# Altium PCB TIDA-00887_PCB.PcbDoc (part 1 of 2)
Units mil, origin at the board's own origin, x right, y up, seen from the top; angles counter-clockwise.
Board outline 2665 x 2727 mil, 4 copper layers (Top Layer, GND, 3p3V, Bottom Layer), stack 61.2 mil thick; 96 components, 53 nets, 301 pads, 167 vias.
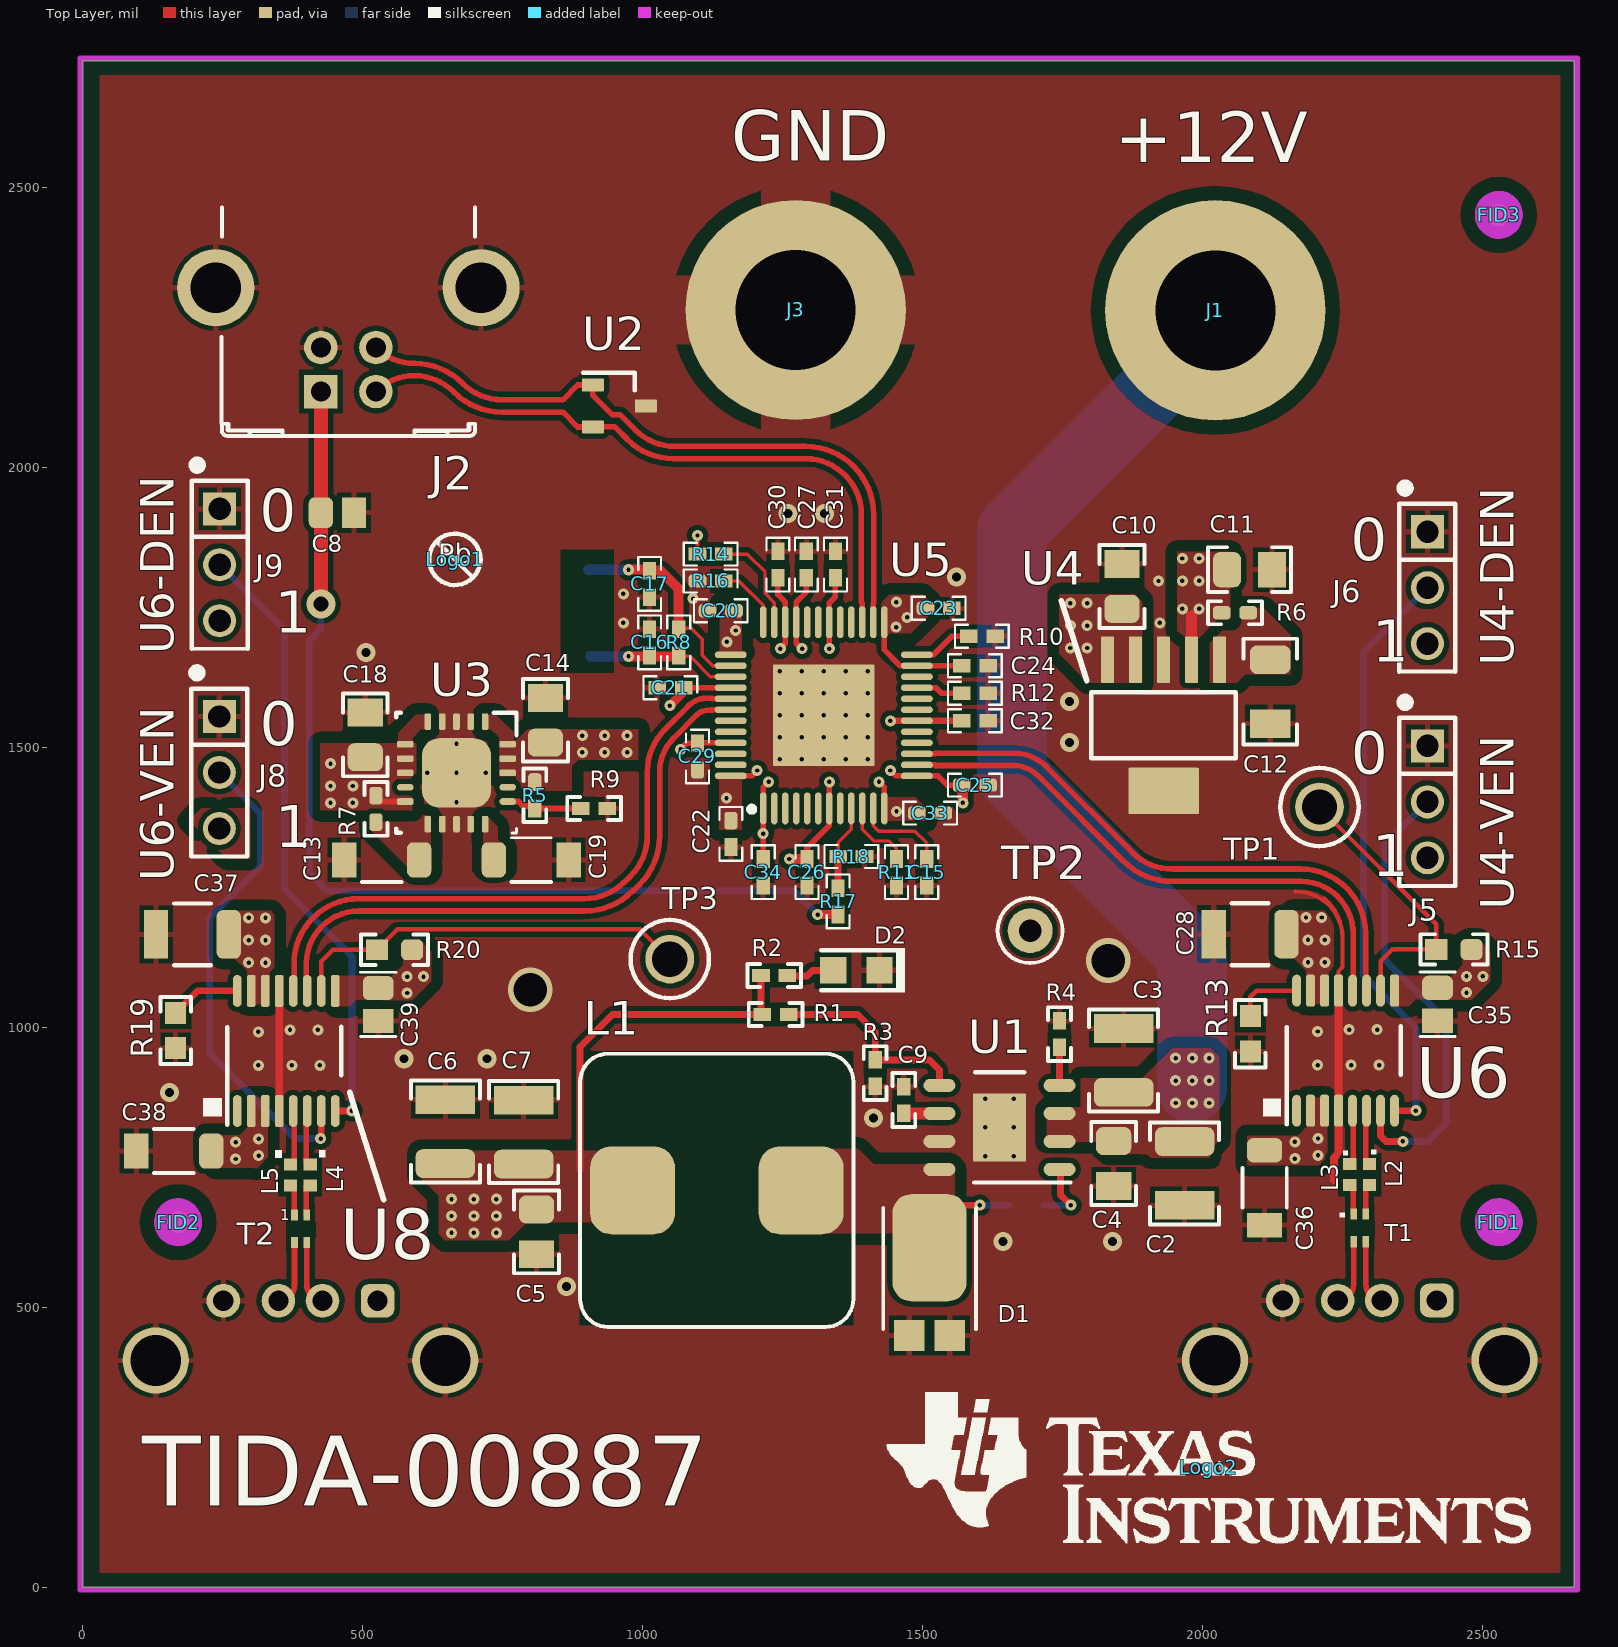
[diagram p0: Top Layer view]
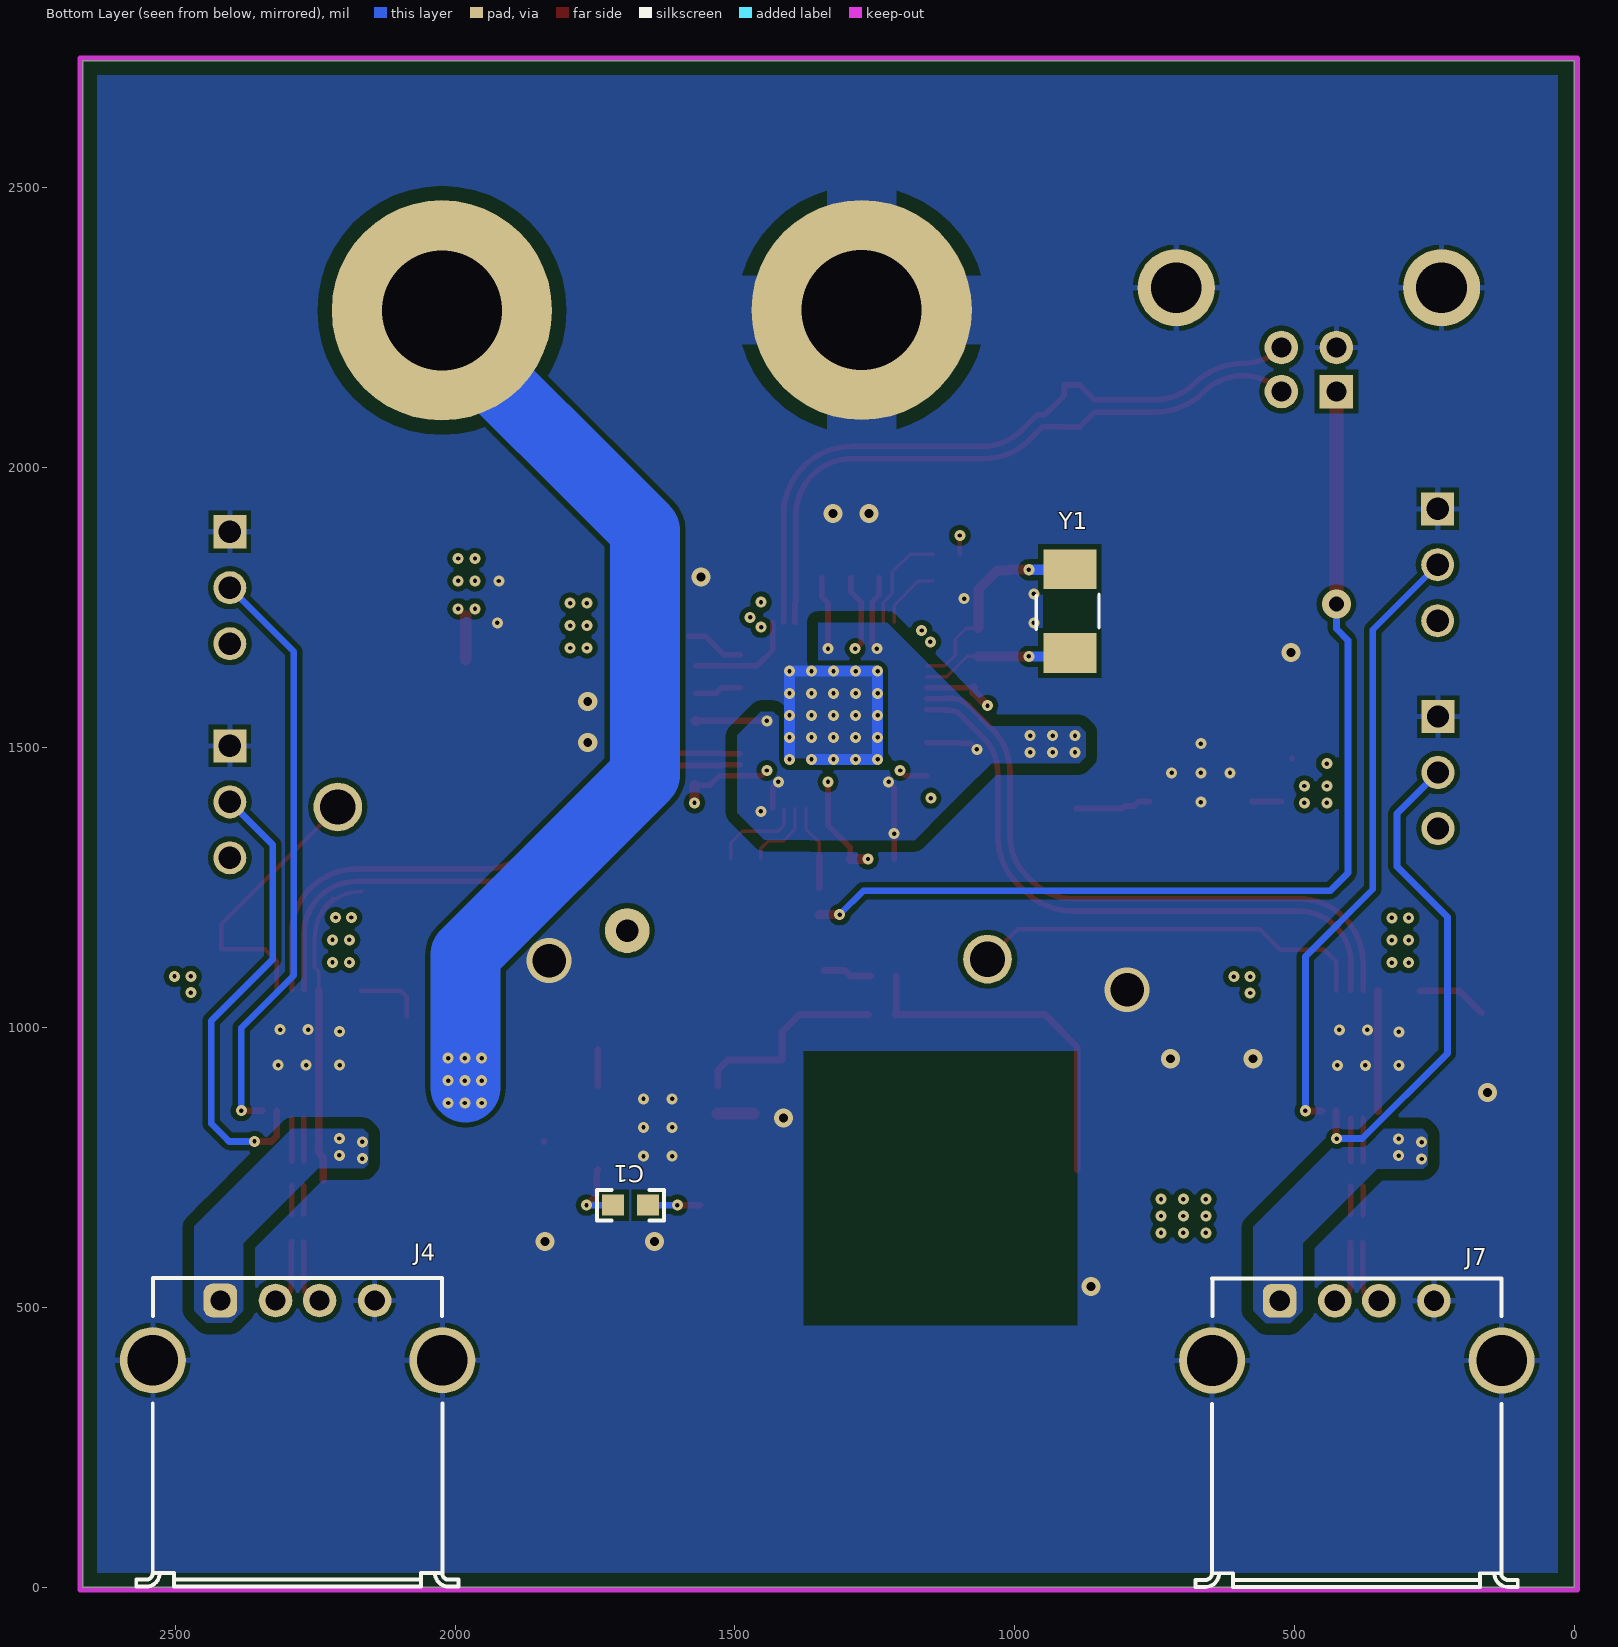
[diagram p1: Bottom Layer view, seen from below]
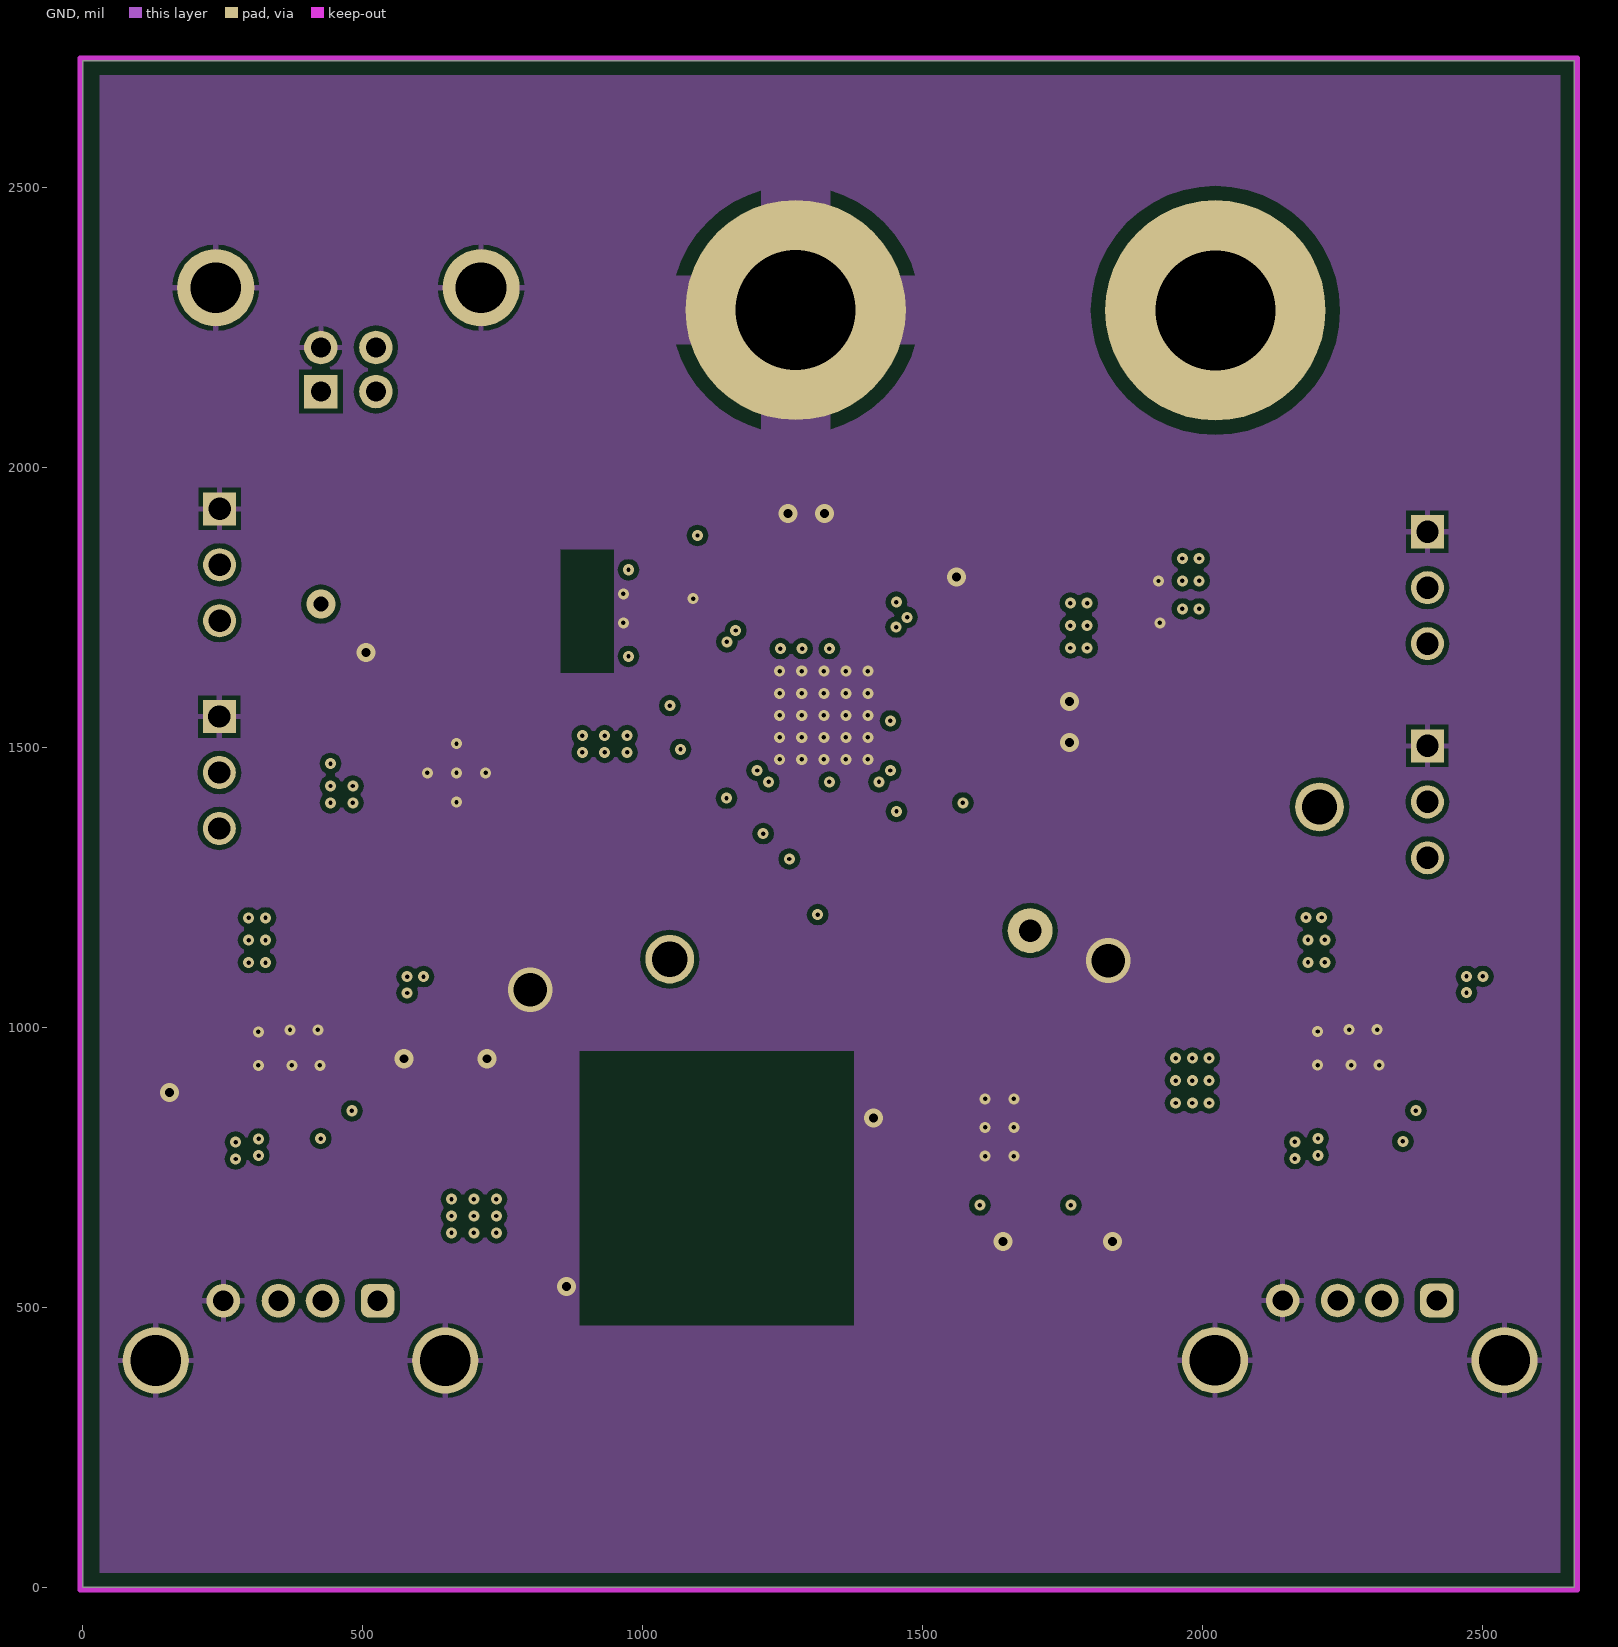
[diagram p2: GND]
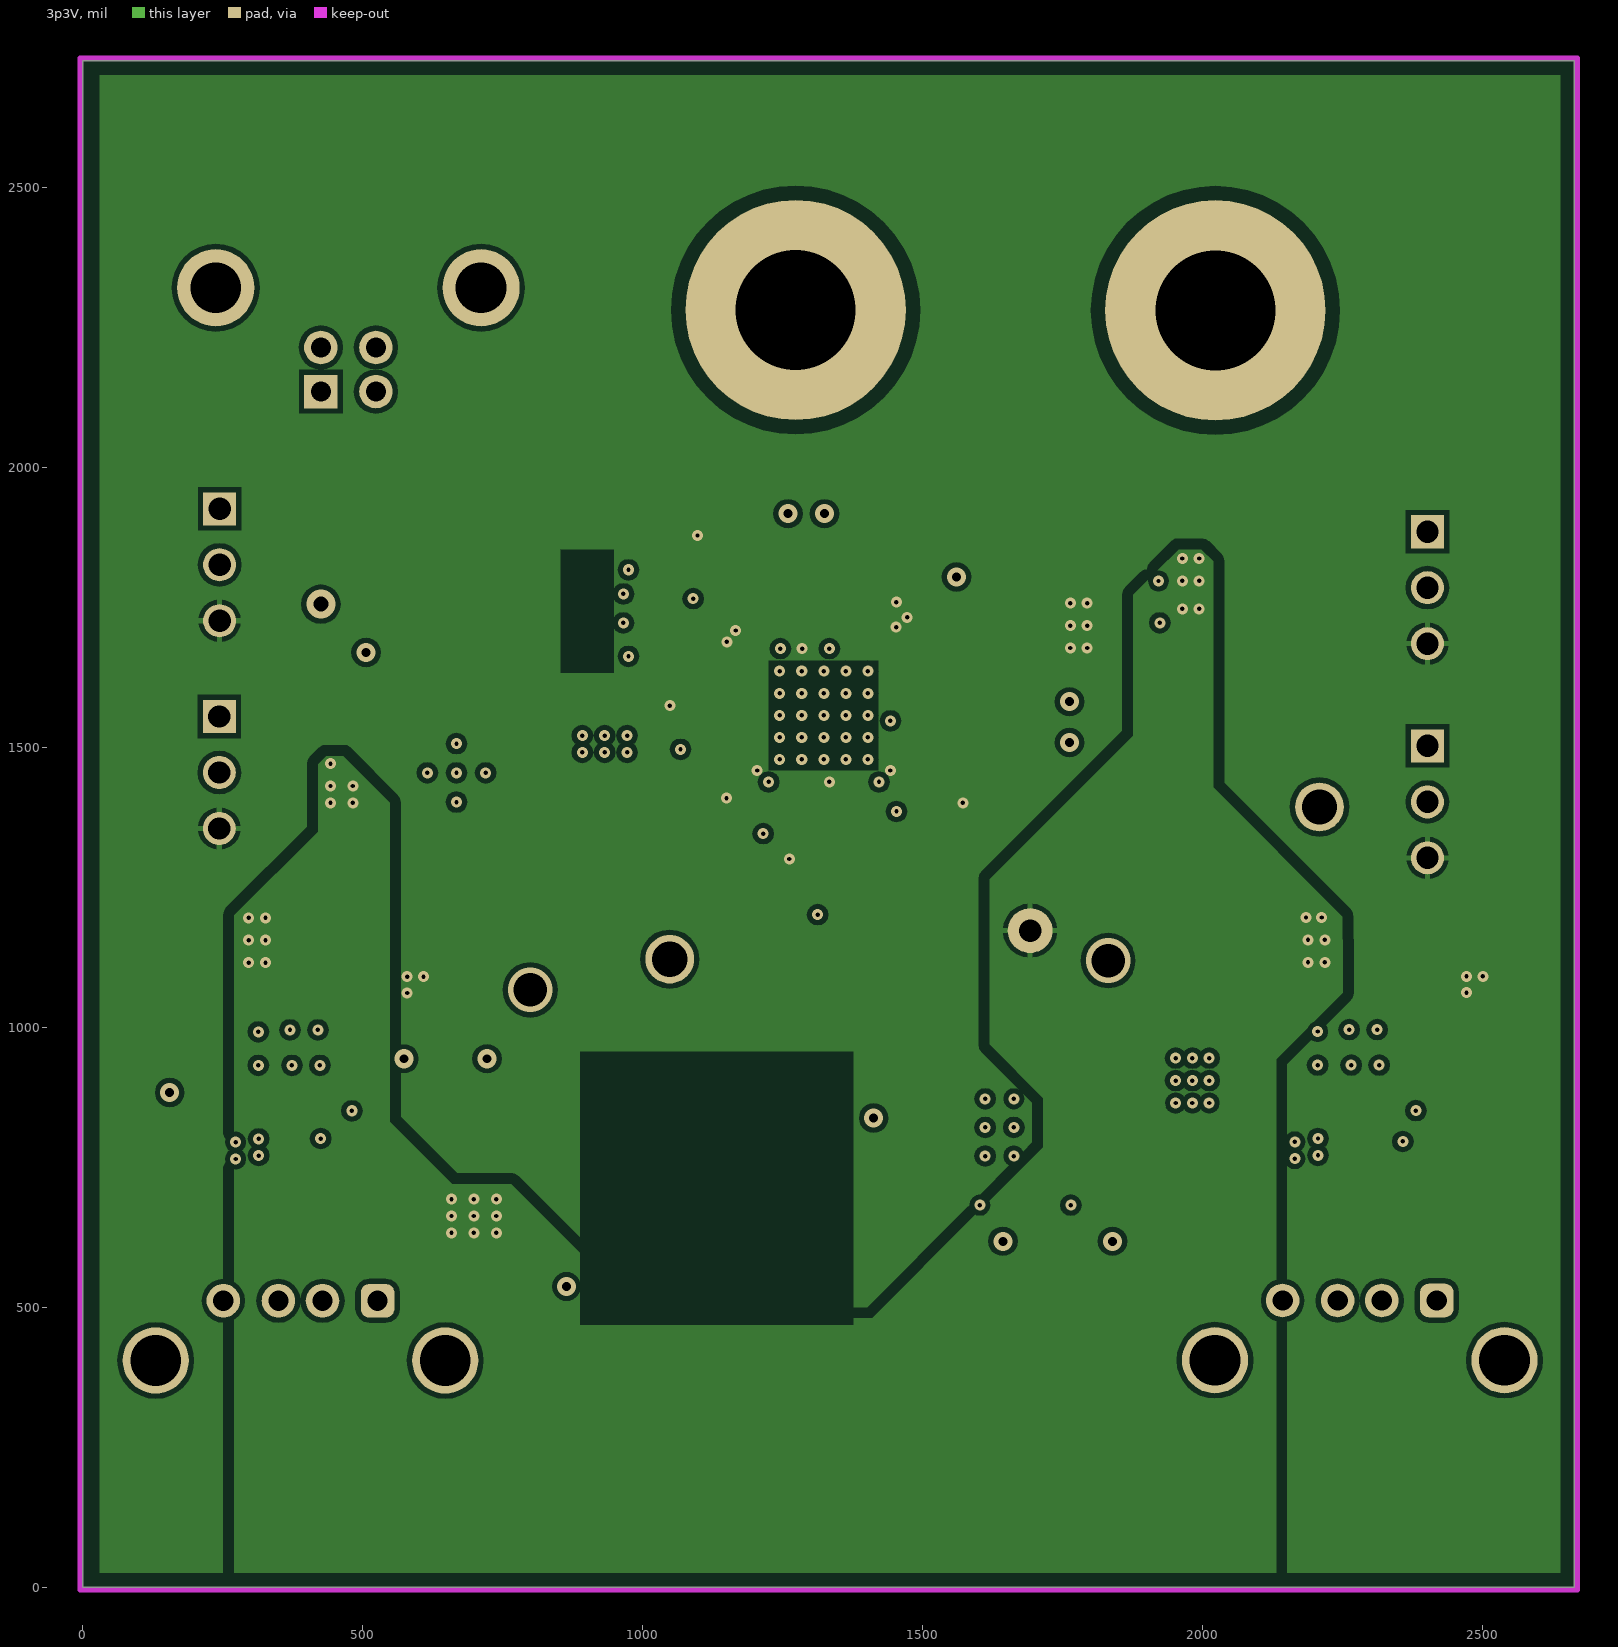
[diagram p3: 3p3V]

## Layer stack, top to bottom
Top Solder: solder mask 0.4, Solder Resist, Dk 3.5
Top Layer: signal copper 1.417
Dielectric1: core 5.5, FR408HR, Dk 3.6
GND: signal copper 1.417
Dielectric 2: prepreg 44.532, FR4, Dk 4.2
3p3V: signal copper 1.417
Dielectric 3: core 5.5, FR408HR, Dk 3.6
Bottom Layer: signal copper 1.417
Bottom Solder: solder mask 0.4, Solder Resist, Dk 3.5

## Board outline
0,0 2665,0 2665,2727 0,2727

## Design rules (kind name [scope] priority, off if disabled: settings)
AcuteAngle [All] p1: minimum=4.50000000000000E+0001 checktracksonly=FALSE
AssemblyTestPointUsage [All] p1: valid=2
Clearance Clearance_Poly_to_Poly_Cap [InPolygon and InNet('NetC7_2') vs InPolygon] p1: gap=5
Clearance Clearance_Keepouts [((IsTrack Or IsArc) And Not InPoly) And IsFree and IsKeepOut vs ((IsTrack Or IsArc) And Not InPoly) And IsFree and IsKeepOut] p2: gap=0
Clearance Clearance_BoardEdge_MountingHoles [OnCopper and InComponentClass('Mounting Holes') vs IsKeepOut] p3: gap=40
Clearance Clearance_BoardEdge_Poly [OnCopper and InPoly vs IsKeepOut] p4: gap=25
Clearance Clearance_BoardEdge [OnCopper and Not InComponentClass('Logo') and not InComponentClass('FiducialMark') and not InRegion(1000,500,4000,800) and Not IsKeepout vs IsKeepOut] p5: gap=62
Clearance Clearance_Poly_GND_J3 [InPadClass('GND')] p6: gap=25
Clearance Clearance_Poly_to_Poly [InPolygon and not InPolygonClass('Star') vs InPolygon] p7: gap=20
Clearance Clearance_Poly [InPolygon and not InPolygonClass('Star')] p8: gap=9
Clearance [All] p9: gap=3.93
ComponentClearance ComponentClearance_BigCap [InComponentClass('BigCap')] p1: gap=0 collisioncheckmode=3 verticalgap=0 showdistances=FALSE
ComponentClearance ComponentClearance_MountingHoles_FiducialMarks [InComponentClass('Mounting Holes') vs InComponentClass('FiducialMark')] p2: gap=50 collisioncheckmode=3 verticalgap=11.3 showdistances=FALSE
ComponentClearance ComponentClearance_Shunt [InComponentClass('Header') vs InComponentClass('Shunt')] p3: gap=0 collisioncheckmode=3 verticalgap=0 showdistances=FALSE
ComponentClearance ComponentClearance_Logo [InComponentClass('Logo')] p4: gap=25 collisioncheckmode=3 verticalgap=11.2 showdistances=FALSE
ComponentClearance ComponentClearance_ScrewToNut [(HasFootprint('NY PMS 440 0025 PH')) vs (HasFootprint('Keystone_1902C'))] p5: gap=5 collisioncheckmode=3 verticalgap=11.1 showdistances=FALSE
ComponentClearance ComponentClearance_MountingHoles [InComponentClass('Mounting Holes')] p6: gap=250 collisioncheckmode=3 verticalgap=100000 showdistances=FALSE
ComponentClearance ComponentClearance_THtoSMT [IsThruComponent vs IsSMTComponent] p7: gap=78 collisioncheckmode=3 verticalgap=30 showdistances=FALSE
ComponentClearance ComponentClearance_THtoTH [IsThruComponent or not (InComponentClass('BigCap') and InComponentClass('BigResistor')) vs IsThruComponent] p8: gap=63 collisioncheckmode=3 verticalgap=30 showdistances=FALSE
ComponentClearance [All] p9: gap=9 collisioncheckmode=3 verticalgap=9 showdistances=FALSE
ComponentClearance ComponentClearance_SmallPassives [HasFootprint('0201*') or HasFootprint('0402*') or HasFootprint('0508') or HasFootprint('0603*') or HasFootprint('0612') or HasFootprint('0805*') or HasFootprint('0815*') or HasFootprint('0830*') or HasFootprint('1206*') or HasFootprint('1210*') or HasFootprint('1808*') or HasFootprint('1812*') or HasFootprint('1825*') or HasFootprint('2010*') or HasFootprint('2220*') or HasFootprint('2225*') or HasFootprint('2512*') or HasFootprint('2728*') or HasFootprint('3518*') vs HasFootprint('0201*') or HasFootprint('0402*') or HasFootprint('0508') or HasFootprint('0603*') or HasFootprint('0612') or HasFootprint('0805*') or HasFootprint('0815*') or HasFootprint('0830*') or HasFootprint('1206*') or HasFootprint('1210*') or HasFootprint('1808*') or HasFootprint('1812*') or HasFootprint('1825*') or HasFootprint('2010*') or HasFootprint('2220*') or HasFootprint('2225*') or HasFootprint('2512*') or HasFootprint('2728*') or HasFootprint('3518*')] p10: gap=19 collisioncheckmode=3 verticalgap=11 showdistances=FALSE
DiffPairsRouting [All] p1: maxlimit=12 minlimit=12 mostfreqgap=12 toplayer_minwidth=10 toplayer_maxwidth=10.01 toplayer_prefwidth=10.01 midlayer1_minwidth=10 midlayer1_maxwidth=10.01 midlayer1_prefwidth=10.01 midlayer2_minwidth=10 midlayer2_maxwidth=10.01 midlayer2_prefwidth=10.01 bottomlayer_minwidth=10 bottomlayer_maxwidth=10.01 bottomlayer_prefwidth=10.01 maxuncoupledlength=2000
FabricationTestPointUsage TestPointUsage [All] p1: valid=2 allowmultiple=FALSE
FabricationTestpoint Testpoint [All] p1: side=3 testpointundercomponent=TRUE minsize=40 maxsize=100 preferedsize=60 minholesize=0 maxholesize=40 preferedholesize=32 testpointgrid=1 allowsidetop=TRUE allowsidebottom=TRUE usegrid=TRUE gridtolerance=0.01
FanoutControl Fanout_LCC [IsLCC] p1: bgadir=Out bgaviamode=Centered fanoutstyle=Auto fanoutdirection=Alternating viagrid=1 // Fanout_LCC (Default Rule)
FanoutControl Fanout_BGA [IsBGA] p2: bgadir=Out bgaviamode=Centered fanoutstyle=Auto fanoutdirection=Alternating viagrid=1 // Fanout_BGA (Default Rule)
FanoutControl Fanout_Default [All] p4: bgadir=Out bgaviamode=Centered fanoutstyle=Auto fanoutdirection=Alternating viagrid=1 // Fanout_Default (Default Rule)
FanoutControl Fanout_Small [(CompPinCount < 5)] p5: bgadir=Out bgaviamode=Centered fanoutstyle=Auto fanoutdirection=OutThenIn viagrid=1 // Fanout_Small (Default Rule)
HoleSize [All] p1: absolutevalues=TRUE maxlimit=251 minlimit=7.8 maxpercent=80.000 minpercent=20.000
MinimumAnnularRing MinimumAnnularRing_ThermalPadVias [IsVia and InAnyComponent] p1: minimumring=5.91
MinimumAnnularRing [All] p2: minimumring=5
MinimumSolderMaskSliver MinimumSolderMaskSliver_Logo [InComponentClass('Logo') vs InComponentClass('Logo')] p1: minsoldermaskwidth=0.7
MinimumSolderMaskSliver [All] p2: minsoldermaskwidth=3.94
PlaneConnect [not (IsVia or IsRoundedRectangularPad)] p1: planeconnectstyle=Relief reliefexpansion=10 reliefentries=4 reliefconductorwidth=10 reliefairgap=10
PolygonConnect RoundedPad_GND [InPadClass('GND')] p1: connectstyle=Relief reliefconductorwidth=125 reliefentries=4 polygonreliefangle="90 Angle" airgapwidth=25
PolygonConnect RoundedPad_Direct [IsRoundedRectangularPad] p2: connectstyle=Direct reliefconductorwidth=10 reliefentries=4 polygonreliefangle="90 Angle" airgapwidth=8
PolygonConnect PolygonConnect_Power_Pad_1 [InPadClass('PowerPad')] p3: connectstyle=Direct reliefconductorwidth=10 reliefentries=4 polygonreliefangle="90 Angle" airgapwidth=8
PolygonConnect PolygonConnect_VIA [IsVia] p4: connectstyle=Direct reliefconductorwidth=10 reliefentries=4 polygonreliefangle="90 Angle" airgapwidth=8
PolygonConnect PolygonConnect_Banana [InPadClass('Banana')] p5: connectstyle=Relief reliefconductorwidth=40 reliefentries=4 polygonreliefangle="90 Angle" airgapwidth=25
PolygonConnect [not IsVia] p6: connectstyle=Relief reliefconductorwidth=10 reliefentries=4 polygonreliefangle="90 Angle" airgapwidth=8
RoutingVias ThermalPadVias [IsVia and InAnyComponent] p1: holewidth=7.87 width=19.68 viastyle="Through Hole" minholewidth=7.87 minwidth=19.68 maxholewidth=12.99 maxwidth=23.62
RoutingVias [All] p2: holewidth=16 width=34 viastyle="Through Hole" minholewidth=7.87 minwidth=18 maxholewidth=85 maxwidth=85
ShortCircuit ShortCircuit_1 [InPolygonClass('Star') vs InNet('AGND') and InNet('DGND')] p2: allowed=TRUE
SilkToBoardRegionClearance [Not ((IsComment or IsDesignator) And (Hide <> 'False')) and not InRegion(1000,500,4000,800)] p1:
SilkToSilkClearance SilkToSilkClearance_Pb-FreeLogo [(HasFootprint('Pb-Free_Overlay_Medium') OR HasFootprint('Pb-Free_Overlay_Small')) vs (HasFootprint('Pb-Free_Overlay_Medium') OR HasFootprint('Pb-Free_Overlay_Small'))] p1: silktosilkclearance=0
SilkToSilkClearance [All] p2: silktosilkclearance=4
SilkToSolderMaskClearance SilkToComonentPadClearance [IsPad and InAnycomponent] p1: minsilkscreentomaskgap=2 clearancetoexposedcopper=TRUE
SilkToSolderMaskClearance "Silk to Solder Mask Opening" [All] p2: minsilkscreentomaskgap=2 clearancetoexposedcopper=FALSE
SolderMaskExpansion [All] p1: expansion=1.97
Width [All] p1: maxlimit=125 minlimit=5 preferedwidth=11 checkconnectedcopper=TRUE
15 further rules are at their usual default settings.

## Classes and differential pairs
pad class GND: J1-1 J3-1
component class Header: J5 J6 J8 J9
component class TIDA-00887_Sch: C1 C2 C3 C4 C5 C6 C7 C8 C9 C10 C11 C12 C13 C14 C15 C16 C17 C18 C19 C20 C21 C22 C23 C24 C25 C26 C27 C28 C29 C30 C31 C32 C33 C34 C35 C36 C37 C38 C39 D1 D2 J1 J2 J3 J4 J5 J6 J7 J8 J9 L1 L2 L3 L4 L5 R1 R2 R3 R4 R5 R6 R7 R8 R9 R10 R11 R12 R13 R14 R15 R16 R17 R18 R19 R20 T1 T2 TP1 TP2 TP3 U1 U2 U3 U4 U5 U6 U8 Y1
component class IsEdgeConnector: J2
component class AssemblyNote: ZZ1 ZZ2 ZZ3
component class FiducialMark: FID1 FID2 FID3
component class TIDA-00887_Hardware: FID1 FID2 FID3 Logo1 Logo2 ZZ1 ZZ2 ZZ3
component class Logo: Logo2
pad class PowerPad: C2-2 C3-2 C4-2 C25-2 J4-1 J7-1 U1-2 U1-3 U1-6 U1-7 U1-8 U5-12 U5-13 U5-25 U5-37 U5-48 U6-4 U6-13
differential pair DP2_SYS: +DP2_SYS_P -DP2_SYS_N
differential pair UP1: +UP1_P -UP1_N
differential pair DP1_SYS: +DP1_SYS_P -DP1_SYS_N
differential pair DP2_CON: +DP1_CON_P -DP1_CON_N
differential pair DP2_CON: +DP2_CON_P -DP2_CON_N

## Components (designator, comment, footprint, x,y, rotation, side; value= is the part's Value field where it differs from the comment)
C1 "GRM188R71C104KA01D" 0603#1 1686.75,682.33 r0 bottom
C2 "GRM32ER71H475KA88L" 1210#1 1968.53,739 r90 top
C3 "GRM32ER71H475KA88L" 1210#1 1859.53,941 r270 top
C4 "GRM21BR71H224KA01L" 0805_HV#1 1841.75,756.84 r90 top
C5 "GRM21BR71E105KA99L" 0805_HV#2 810.46,634.68 r270 top
C6 "GRM32ER61C476ME15L" 1210#2 647.53,813.84 r90 top
C7 "GRM32ER61C476ME15L" 1210#2 787.53,813 r90 top
C8 "C2012X7R0J106M125AB" 0805L 454.64,1919.79 r0 top
C9 "GRM155R71C223KA01D" 0402#1 1466.74,870.33 r270 top
C10 "0805YD106MAT2A" 0805_HV#2 1856.54,1788 r90 top
C11 "0805YD106MAT2A" 0805_HV#2 2084.54,1818 r0 top
C12 "12063C564KAT2A" 1206 2121.54,1600 r90 top
C13 "202R18W102KV4E" 1206_190#1 533.84,1299.39 r0 top
C14 "0805YD106MAT2A" 0805_HV#2 826.43,1548.84 r90 top
C15 "GRM155R70J105MA12D" 0402#1 1507.66,1277.32 r90 top
C16 "GRM1555C1H200JA01D" 0402#1 1012.55,1688.14 r90 top
C17 "GRM1555C1H200JA01D" 0402#1 1012.55,1792.5 r270 top
C18 "0805YD106MAT2A" 0805_HV#2 504.43,1522.84 r90 top
C19 "202R18W102KV4E" 1206_190#1 801.17,1299.39 r180 top
C20 "GRM155R71H103KA88D" 0402#2 1139.7,1744.48 r0 top
C21 "GRM155R71H103KA88D" 0402#1 1049.7,1606.95 r0 top
C22 "TMK105B7104MV-FR" 0402#3 1157.8,1345.95 r90 top
C23 "TMK105B7104MV-FR" 0402#3 1529.13,1748.94 r180 top
C24 "GRM155R71H103KA88D" 0402#1 1593.8,1646.33 r180 top
C25 "TMK105B7104MV-FR" 0402#2 1593.8,1432.94 r180 top
C26 "GRM155R71H103KA88D" 0402#1 1293.8,1277.32 r90 top
C27 "TMK105B7104MV-FR" 0402#1 1292.64,1827 r270 top
C28 "C1210C107M8PACTU" 1210_280 2085.53,1166.56 r180 top
C29 "GRM155R71H103KA88D" 0402#4 1098.12,1484.12 r90 top
C30 "GRM155R71H103KA88D" 0402#1 1241.75,1827 r270 top
C31 "GRM155R71H103KA88D" 0402#1 1344.64,1827 r270 top
C32 "GRM155R71H103KA88D" 0402#1 1593.8,1547.9 r180 top
C33 "TMK105B7104MV-FR" 0402#2 1513.8,1382.94 r180 top
C34 "TMK105B7104MV-FR" 0402#1 1215.54,1277.32 r90 top
C35 "C2012X7R0J106M125AB" 0805L 2420.56,1041.24 r270 top
C36 "GCM31CR72A105KA03" 1206_190#2 2111.53,713.53 r270 top
C37 "C1210C107M8PACTU" 1210_280 195.65,1166.33 r180 top
C38 "GCM31CR72A105KA03" 1206_190#2 162.32,779.01 r180 top
C39 "C2012X7R0J106M125AB" 0805L 527.68,1040.77 r270 top
D1 "PDS560-13" PowerDI5 1512.75,527.84 r90 top
D2 "LTST-C171GKT" LED_LTST-C171 1382.03,1102.15 r0 top
FID1 "Fiducial" Fiducial10-20 2530,652 r0 top
FID2 "Fiducial" Fiducial10-20 170,652 r0 top
FID3 "Fiducial" Fiducial10-20 2530,2452 r90 top
J1 "575-4" Keystone_575-4#1 2023.53,2282 r90 top
J2 "67068-8000" MOLEX_67068-8000 474.32,2321.69 r90 top
J3 "575-4" Keystone_575-4#2 1273.53,2282 r90 top
J4 "292303-4" CONN_TE_292303-4 2281.53,512 r180 bottom
J5 "PEC03SAAN" CONN_PEC03SAAN 2402.54,1403 r270 top
J6 "PEC03SAAN" CONN_PEC03SAAN 2402.54,1785.73 r270 top
J7 "292303-4" CONN_TE_292303-4 388.66,511.53 r180 bottom
J8 "PEC03SAAN" CONN_PEC03SAAN 243.59,1455.52 r270 top
J9 "PEC03SAAN" CONN_PEC03SAAN 244.15,1826.73 r270 top
L1 "744325550" WE-HC6 1132.62,708.84 r180 top
L2 "LQG15HS10NJ02D" IND_LQG15H 2298.84,737 r270 top
L3 "LQG15HS10NJ02D" IND_LQG15H 2263.53,737 r270 top
L4 "LQG15HS10NJ02D" IND_LQG15H 405.96,736.53 r270 top
L5 "LQG15HS10NJ02D" IND_LQG15H 370.66,736.53 r270 top
Logo1 "Pb-Free Symbol" Pb-Free_Overlay_Small 664.53,1836.49 r0 top
Logo2 "Texas Instruments" TI_Stacked_Overlay_Medium 2012,214 r0 top
R1 "CRCW0402100KDHEDP" 0402#1 1237.75,1022.95 r0 top
R2 "CRCW0402255RFKED" 0402#1 1235.21,1092.54 r0 top
R3 "CRCW040217K8FKED" 0402#1 1415.74,918.33 r270 top
R4 "CRCW040249K9FKED" 0402#1 1745.03,988 r90 top
R5 "CRCW04021K87FKED" 0402#3 807.43,1414.84 r90 top
R6 "CRCW040230R1FKED" 0402#2 2058.54,1741 r180 top
R7 "CRCW040230R1FKED" 0402#2 523.42,1390.54 r90 top
R8 "CRCW04021M00FKED" 0402#1 1064.49,1688.14 r90 top
R9 "CRCW04024K99FKED" 0402#1 913.35,1391.28 r180 top
R10 "CRCW04029K53FKED" 0402#1 1606.38,1698.94 r0 top
R11 "CRCW04021K00FKED" 0402#1 1453.8,1277.32 r270 top
R12 "CRCW04024K70JNED" 0402#1 1593.8,1597.11 r180 top
R13 "CRCW060386K6FKEA" 0603#1 2086.1,988.7 r90 top
R14 "CRCW04024K70JNED" 0402#1 1121.74,1845.74 r0 top
R15 "CRCW060310K0FKEA" 0603#2 2449.72,1139.29 r0 top
R16 "CRCW04024K70JNED" 0402#4 1121.74,1797.74 r0 top
R17 "CRCW040290K9FKED" 0402#1 1349.39,1225.32 r90 top
R18 "CRCW040210K0DHEDP" 0402#1 1373.02,1305.32 r180 top
R19 "CRCW060386K6FKEA" 0603#1 165.66,994.53 r90 top
R20 "CRCW060310K0FKEA" 0603#2 556.85,1138.82 r0 top
T1 "mcf12102g900" LCCI-44 2281.37,643.57 r0 top
T2 "mcf12102g900" LCCI-44 388.87,642.44 r0 top
TP1 "5008" Keystone5008 2209.53,1394 r0 top
TP2 "5000" Keystone5000 1692.53,1173 r90 top
TP3 "5008" Keystone5008 1048.53,1122 r0 top
U1 "LMR14050SQDDARQ1" DDA0008E_N 1637.74,821.33 r180 top
U2 "TPD2E2U06QDBZRQ1" DBZ0003A_N 958.53,2110.53 r0 top
U3 "TPS74801RGWR" RGW0020A 667.43,1454.84 r270 top
U4 "TPS7A4533DCQR" DCQ0006A_N 1931.03,1539.82 r270 top
U5 "TUSB4020BIPHP" PHP0048C_N 1323.8,1557.74 r90 top
U6 "TPD3S716QDBQRQ1" DBQ0016A_N 2256.2,958.49 r90 top
U8 "TPD3S716QDBQRQ1" DBQ0016A_N 363.32,958.01 r90 top
Y1 "445C25D24M00000" 445C25D24M00000 901.36,1669.14 r90 bottom
ZZ1 "These assemblies are ESD sensitive, ESD precautions shall be observed." AssemblyNote 1644.52,3858.81 r0 top
ZZ2 "These assemblies must be clean and free from flux and all contaminants. Use of no clean flux is not acceptable." AssemblyNote 1644.52,4098.81 r0 top
ZZ3 "These assemblies must comply with workmanship standards IPC-A-610 Class 2, unless otherwise specified." AssemblyNote 1644.52,4338.81 r0 top

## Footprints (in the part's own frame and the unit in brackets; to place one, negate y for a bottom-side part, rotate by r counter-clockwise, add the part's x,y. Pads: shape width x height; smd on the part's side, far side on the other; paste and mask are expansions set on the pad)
0402#1 [mm] "0402 from SM-752 data"
  rect 0.8x0.6 smd: 1(-0.6,0) 2(0.6,0)
  silkscreen extent -1.22,-0.52 1.22,0.52, body extent -0.55,-0.3 0.55,0.3, height 0.6
0402#2 [mm] "0402 from SM-752 data"
  rrect50% 0.8x0.6 smd: 1(-0.6,0) 2(0.6,0)
  silkscreen extent -1.22,-0.52 1.22,0.52, body extent -0.55,-0.3 0.55,0.3, height 0.6
0402#3 [mm] "0402 from SM-752 data"
  rect 0.8x0.6 smd: 1(-0.6,0)
  rrect50% 0.8x0.6 smd: 2(0.6,0)
  silkscreen extent -1.22,-0.52 1.22,0.52, body extent -0.55,-0.3 0.55,0.3, height 0.6
0402#4 [mm] "0402 from SM-752 data"
  rrect50% 0.8x0.6 smd: 1(-0.6,0)
  rect 0.8x0.6 smd: 2(0.6,0)
  silkscreen extent -1.22,-0.52 1.22,0.52, body extent -0.55,-0.3 0.55,0.3, height 0.6
445C25D24M00000 [mm] "CTS 445C25D24M00000"
  rect 1.8x2.4 smd: 1(0,0) 2(3.8,0)
0603#1 [mm] "0603 from SM-752 data"
  rect 1x0.95 smd: 1(-0.8,0) 2(0.8,0)
  silkscreen extent -1.52,-0.69 1.52,0.69, body extent -0.87,-0.47 0.87,0.47, height 1
0603#2 [mm] "0603 from SM-752 data"
  rect 1x0.95 smd: 1(-0.8,0)
  rrect50% 1x0.95 smd: 2(0.8,0)
  silkscreen extent -1.52,-0.69 1.52,0.69, body extent -0.87,-0.47 0.87,0.47, height 1
0805_HV#1 [mil] "0805 with 30mil clearance between pads"
  rect 50x63 smd: 1(-40,0)
  rrect50% 50x63 smd: 2(40,0)
  silkscreen extent -74,-40 74,40, body extent -43,-29 43,29, height 57
0805_HV#2 [mil] "0805 with 30mil clearance between pads"
  rrect50% 50x63 smd: 1(-40,0)
  rect 50x63 smd: 2(40,0)
  silkscreen extent -74,-40 74,40, body extent -43,-29 43,29, height 57
0805L [mm] "0805 from SM-752 data"
  rrect50% 1.1x1.4 smd: 1(-0.75,0)
  rect 1.1x1.4 smd: 2(0.75,0)
  body extent -1.1,-0.72 1.1,0.72, height 1.45
1206 [mm] "1206 from SM-752 data"
  rect 1.3x1.85 smd: 1(-1.45,0)
  rrect50% 1.3x1.85 smd: 2(1.45,0)
  silkscreen extent -2.4,-1.21 2.4,1.21, body extent -1.7,-0.9 1.7,0.9, height 1.35
1206_190#1 [mm] "1206_190"
  rect 1.1x1.6 smd: 1(-1.7,0)
  rrect50% 1.1x1.6 smd: 2(1.7,0)
  silkscreen extent -0.9,-1 0.9,-1, body extent -1.75,-0.95 1.75,0.95, height 1.9
1206_190#2 [mm] "1206_190"
  rrect50% 1.1x1.6 smd: 1(-1.7,0)
  rect 1.1x1.6 smd: 2(1.7,0)
  silkscreen extent -0.9,-1 0.9,1, body extent -1.75,-0.95 1.75,0.95, height 1.9
1210#1 [mm] "1210 from SM-752 data"
  rect 1.3x2.7 smd: 1(-1.45,0)
  rrect50% 1.3x2.7 smd: 2(1.45,0)
  silkscreen extent -2.32,-1.57 2.32,1.57, body extent -1.7,-1.35 1.7,1.35, height 1.35
1210#2 [mm] "1210 from SM-752 data"
  rrect50% 1.3x2.7 smd: 1(-1.45,0)
  rect 1.3x2.7 smd: 2(1.45,0)
  silkscreen extent -2.32,-1.57 2.32,1.57, body extent -1.7,-1.35 1.7,1.35, height 1.35
1210_280 [mm] "SMD, 2-Leads, Body 3.6x2.8mm, Height 2.8mm"
  rrect50% 1.1x2.2 smd: 1(-1.65,0)
  rect 1.1x2.2 smd: 2(1.65,0)
  silkscreen extent -0.84,-1.4 0.84,1.4, body extent -1.8,-1.4 1.8,1.4, height 2.8
AssemblyNote [mil] "Assembly Note"
CONN_PEC03SAAN [mm] "SULLINS"
  rect 1.5x1.5 hole 1.016: 1(-2.54,0)
  round 1.5 hole 1.016: 2(0,0) 3(2.54,0)
  silkscreen extent -4.72,-1.27 3.81,1.27, body extent -3.84,-1.3 3.84,1.3, height 8.38
CONN_TE_292303-4 [mm] "TE Connectivity"
  rrect50% 1.524x1.524 hole 0.92: 1(-3.5,0)
  round 1.524 hole 0.92: 2(-1,0) 3(1,0) 4(3.5,0)
  round 3 hole 2.3: 5(-6.57,-2.71) 6(6.57,-2.71)
  silkscreen extent -7.32,-12.99 7.3,1.01, body extent -8.12,-12.99 8.12,1.01, height 7.67
DBQ0016A_N [mm] "SOP, 16-Leads, Body 4.9x3.9mm, Pitch 0.635mm, IPC Medium Density"
  oval 1.45x0.4 smd: 1(-2.725,2.222) 5(-2.725,-0.318) 6(-2.725,-0.953) 7(-2.725,-1.588) 8(-2.725,-2.222) 10(2.725,-1.587) 11(2.725,-0.952) 12(2.725,-0.317) 16(2.725,2.222)
  rrect50% 1.45x0.4 smd: 2(-2.725,1.587) 3(-2.725,0.952) 4(-2.725,0.317) 9(2.725,-2.222) 13(2.725,0.318) 14(2.725,0.953) 15(2.725,1.588)
  silkscreen extent -3.35,-2.5 1.1,2.68, body extent -3.01,-2.45 3.01,2.45, height 1.63
DBZ0003A_N [mm] "SOT23, 3-Leads, Body 2.9x1.3mm, Pitch 0.95mm, Lead Span 2.4mm, IPC Medium Density"
  rrect17% 1x0.6 smd: 1(-1.2,0.95) 2(-1.2,-0.95) 3(1.2,0)
  silkscreen extent -1.65,0.7 0.7,1.5, body extent -1.26,-1.46 1.26,1.46, height 0.98
DCQ0006A_N [mm] "SOT223, 6-Leads, Body 6.6x7.3mm (max), Pitch 1.27mm, IPC Medium Density"
  rrect17% 2.1x0.6 smd: 1(-2.975,2.54) 2(-2.975,1.27) 3(-2.975,0) 4(-2.975,-1.27) 5(-2.975,-2.54)
  rrect5% 2.1x3.2 smd: 6(2.975,0)
  silkscreen extent -1.5,-3.27 1.5,3.28, body extent -3.54,-3.25 3.54,3.25, height 1.8
DDA0008E_N [mm]
  rrect100% 1.45x0.6 smd: 1(-2.725,1.905) 2(-2.725,0.635) 3(-2.725,-0.635) 4(-2.725,-1.905) 5(2.725,-1.905) 6(2.725,-0.635) 7(2.725,0.635) 8(2.725,1.905)
  rrect4% 2.4x3.1 smd: 9(0,0)
  silkscreen extent -3.22,-2.5 1.15,2.5, body extent -3.01,-2.45 3.01,2.45, height 1.7
Fiducial10-20 [mm]
  round 1 smd mask+0.5: 1(0,0)
  Top Layer keep-out circle w1.178: c0,0 r0.5
IND_LQG15H [mm] "MuRata"
  rect 0.55x0.6 smd: 1(-0.475,0) 2(0.475,0)
  body extent -0.52,-0.27 0.52,0.27, height 0.55
Keystone5000 [mil] "For Keystone 500x miniature loop terminals"
  round 80 hole 40: 1(0,0)
  silkscreen extent -58,-58 58,58, body extent -49,-49 49,49, height 182
Keystone5008 [mil] "Keystone Compact loops"
  round 87 hole 63: 1(0,0)
  silkscreen extent -70,-70 70,70, body extent -63,-63 62,63, height 225
Keystone_575-4#1 [mm] "Banana Jack"
  round 10 hole 5.45: 1(-0.018,0)
  body extent -3.95,-3.95 3.92,3.93, height 2.36
Keystone_575-4#2 [mm] "Banana Jack"
  round 10 hole 5.45: 1(0,0)
  body extent -3.95,-3.95 3.92,3.93, height 2.36
LCCI-44 [mm] "Pulse Engineering recommended land pattern"
  rect 0.3x0.5 smd paste+0 mask+0: 1(-0.275,0.575) 2(-0.275,-0.675) 3(0.275,0.575) 4(0.275,-0.675)
LED_LTST-C171 [mm] "LITE-ON"
  rect 1.2x1.2 smd: 1(-1.05,0) 2(1.05,0)
  silkscreen extent -1.6,-1 2.2,1, body extent -1.05,-0.67 1.05,0.68, height 0.8
MOLEX_67068-8000 [mm] "MOLEX"
  rect 1.524x1.524 hole 0.914: 1(-4.71,1.25)
  round 1.524 hole 0.914: 2(-4.71,-1.25) 3(-2.71,-1.25) 4(-2.71,1.25)
  round 3.5 hole 2.3: 5(0,6.02) 6(0,-6.02)
  silkscreen extent -6.72,-5.75 3.65,5.75, body extent -6.72,-7.43 10.28,7.43, height 11.02
Pb-Free_Overlay_Small [mil]
  silkscreen extent -46,-46 46,46
PHP0048C_N [mm] "Thin QFP, 48-Leads, Body 7x7mm, Pitch 0.5mm, Thermal Pad 3x3mm, IPC Medium Density"
  rrect100% 1.45x0.3 smd: 1(-4.225,2.75) 2(-4.225,2.25) 3(-4.225,1.75) 4(-4.225,1.25) 5(-4.225,0.75) 6(-4.225,0.25) 7(-4.225,-0.25) 8(-4.225,-0.75) 9(-4.225,-1.25) 10(-4.225,-1.75) 11(-4.225,-2.25) 12(-4.225,-2.75) 25(4.225,-2.75) 26(4.225,-2.25) 27(4.225,-1.75) 28(4.225,-1.25) 29(4.225,-0.75) 30(4.225,-0.25) 31(4.225,0.25) 32(4.225,0.75) 33(4.225,1.25) 34(4.225,1.75) 35(4.225,2.25) 36(4.225,2.75)
  rrect100% 0.3x1.45 smd: 13(-2.75,-4.225) 14(-2.25,-4.225) 15(-1.75,-4.225) 16(-1.25,-4.225) 17(-0.75,-4.225) 18(-0.25,-4.225) 19(0.25,-4.225) 20(0.75,-4.225) 21(1.25,-4.225) 22(1.75,-4.225) 23(2.25,-4.225) 24(2.75,-4.225) 37(2.75,4.225) 38(2.25,4.225) 39(1.75,4.225) 40(1.25,4.225) 41(0.75,4.225) 42(0.25,4.225) 43(-0.25,4.225) 44(-0.75,4.225) 45(-1.25,4.225) 46(-1.75,4.225) 47(-2.25,4.225) 48(-2.75,4.225)
  rrect2% 4.6x4.6 smd: 49(0,0)
  silkscreen extent -4.39,3.15 -4.14,3.4, body extent -4.51,-4.51 4.51,4.51, height 1.2
PowerDI5 [mm] "Diodes Inc recommended land pattern, ap02001.pdf rev 60"
  rect 1.4x1.39 smd: 1(-1.991,0.92) 2(-1.991,-0.92)
  rrect50% 4.86x3.36 smd: 3(1.991,0)
  silkscreen extent -1.7,-2.1 3.8,2.1, body extent -2.27,-2.03 4.33,2.03, height 1.17
RGW0020A [mm] "QFN, 20-Leads, Body 5x5mm, Pitch 0.65mm, Thermal Pad 3.15x3.15mm, TI Recommended"
  rrect50% 0.75x0.3 smd: 1(-2.325,1.3) 2(-2.325,0.65) 3(-2.325,0) 4(-2.325,-0.65) 5(-2.325,-1.3) 11(2.325,-1.3) 12(2.325,-0.65) 13(2.325,0) 14(2.325,0.65) 15(2.325,1.3)
  rrect50% 0.3x0.75 smd: 6(-1.3,-2.325) 7(-0.65,-2.325) 8(0,-2.325) 10(1.3,-2.325) 18(0,2.325) 19(-0.65,2.325) 20(-1.3,2.325)
  oval 0.3x0.75 smd: 9(0.65,-2.325) 16(1.3,2.325) 17(0.65,2.325)
  rrect50% 3.15x3.15 smd paste-1.575: 21(0,0)
  silkscreen extent -2.73,-2.73 2.73,2.73, body extent -2.58,-2.57 2.57,2.58, height 1.01
TI_Stacked_Overlay_Medium [mil]
  silkscreen extent -576,-136 576,135
WE-HC6 [mm] "Wurth Electronik recommended land pattern"
  rrect50% 3.85x4 smd: 1(-3.825,0) 2(3.825,0)
  silkscreen extent -6.2,-6.2 6.2,6.2, body extent -5.76,-5.36 5.74,5.34, height 5

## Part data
C1: "CAP, CERM, 0.1 µF, 16 V, +/- 10%, X7R, 0603"
C2 C3: "CAP, CERM, 4.7 µF, 50 V, +/- 10%, X7R, 1210"
C4: "CAP, CERM, 0.22 µF, 50 V, +/- 10%, X7R, 0805"
C5: "CAP, CERM, 1 µF, 25 V, +/- 10%, X7R, 0805"
C6 C7: "CAP, CERM, 47 µF, 16 V, +/- 20%, X5R, 1210"
C8 C35 C39: "CAP, CERM, 10 µF, 6.3 V, +/- 20%, X7R, 0805"
C9: "CAP, CERM, 0.022 µF, 16 V, +/- 10%, X7R, 0402"
C10 C11 C14 C18: "CAP, CERM, 10 µF, 16 V, +/- 20%, X5R, 0805"
C12: "CAP, CERM, 0.56 µF, 25 V, +/- 10%, X7R, 1206"
C13 C19: "CAP, CERM, 1000 pF, 2000 V, +/- 10%, X7R, 1206_190"
C15: "CAP, CERM, 1 µF, 6.3 V, +/- 20%, X7R, 0402"
C16 C17: "CAP, CERM, 20 pF, 50 V, +/- 5%, C0G/NP0, 0402"
C20 C21 C24 C26 C29 C30 C31 C32: "CAP, CERM, 0.01 µF, 50 V, +/- 10%, X7R, 0402"
C22 C23 C25 C27 C33 C34: "CAP, CERM, 0.1 µF, 25 V, +/- 20%, X7R, 0402"
C28 C37: "CAP, CERM, 100 µF, 10 V, +/- 20%, X5R, 1210"
C36 C38: "CAP, CERM, 1 µF, 100 V, +/- 10%, X7R, AEC-Q200 Grade 1, 1206_190"
D1: "Diode, Schottky, 60 V, 5 A, PowerDI5"
D2: "LED, Green, SMD"
FID1 FID2 FID3: "Fiducial mark.  There is nothing to buy or mount."
J1 J3: "Standard Banana Jack, Uninsulated, 5.5mm"
J2: "Connector, Receptacle, USB TYPE B, R/A, Top Mount TH"
J4 J7: "Connector, Receptacle, USB Type A, R/A, Top Mount TH"
J5 J6 J8 J9: "Header, 100mil, 3x1, Tin, TH"
L1: "Inductor, Shielded Drum Core, Superflux, 5.5 µH, 10 A, 0.0112 ohm, SMD"
L2 L3 L4 L5: "Inductor, Multilayer, Air Core, 10nH, 0.3A, 0.26 ohm, SMD"
Logo1: library part Pb-Free
Logo2: library part TI_Logo, "Texas Instrument Corporate Signature"
R1: "RES, 100 k, 0.5%, 0.063 W, 0402"
R2: "RES, 255, 1%, 0.063 W, 0402"
R3: "RES, 17.8 k, 1%, 0.063 W, 0402"
R4: "RES, 49.9 k, 1%, 0.063 W, 0402"
R5: "RES, 1.87 k, 1%, 0.063 W, 0402"
R6 R7: "RES, 30.1, 1%, 0.063 W, 0402"
R8: "RES, 1.00 M, 1%, 0.063 W, 0402"
R9: "RES, 4.99 k, 1%, 0.063 W, 0402"
R10: "RES, 9.53 k, 1%, 0.063 W, 0402"
R11: "RES, 1.00 k, 1%, 0.063 W, 0402"
R12 R14 R16: "RES, 4.7 k, 5%, 0.063 W, 0402"
R13 R19: "RES, 86.6 k, 1%, 0.1 W, 0603"
R15 R20: "RES, 10.0k ohm, 1%, 0.1W, 0603"
R17: "RES, 90.9 k, 1%, 0.063 W, 0402"
R18: "RES, 10.0 k, 0.5%, 0.063 W, 0402"
T1 T2: library part PA2750NL, "SMT Common Mode Choke"
TP1 TP3: "Test Point, Compact, Orange, TH"
TP2: "Test Point, Miniature, Red, TH"
U1: "SIMPLE SWITCHER 40 V 5 A, 2.2 MHz Step-Down Converter with 40 uA IQ, DDA0008E"
U2: "Dual-Channel High-Speed ESD Protectiong Device, DBZ0003A"
U3: "Single Output LDO, 1.5 A, Adjustable 0.8 to 3.6 V Output, 0.8 to 5.5 V Input, with Programmable Soft Start, 20-pin VQFN (RGW), -40 to 125 degC, Green (RoHS & no Sb/Br)"
U4: "Single Output Fast Transient Response LDO, 1.5 A, Fixed 3.3 V Output, 2.1 to 20 V Input, 6-pin SOT-223 (DCQ), -40 to 125 degC, Green (RoHS & no Sb/Br)"
U5: library part TSB41AB1PHPG4, "400 Mbps IEEE 1394a One-Port Cable Transceiver / Arbiter, 3.3V, 0 to 70 degC, 48-Pin HTQFP (PHP), Green (RoHS & no Sb/Br)"
U6 U8: "AUTOMOTIVE USB 2.0 Interface Protection with Short-to-Battery, Short-to-Ground Protection, and Adjustable Current Limit, DBQ0016A"
Y1: library part ECS-240-20-5PX-TR, "Crystal, 24.000MHz, 20pF, SMD"
ZZ1 ZZ2 ZZ3: library part AssemblyNote

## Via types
v1: diameter 19.68, hole 7.87, Top Layer to Bottom Layer, tented both sides, 115 vias
v2: diameter 19.68, hole 7.87, Top Layer to Bottom Layer, 30 vias
v3: diameter 34, hole 16, Top Layer to Bottom Layer, tented both sides, 13 vias
v4: diameter 19.68, hole 7.87, Top Layer to Bottom Layer, tented top, 6 vias
v5: diameter 80, hole 60, Top Layer to Bottom Layer, 2 vias
v6: diameter 51.77, hole 26.7, Top Layer to Bottom Layer, 1 vias

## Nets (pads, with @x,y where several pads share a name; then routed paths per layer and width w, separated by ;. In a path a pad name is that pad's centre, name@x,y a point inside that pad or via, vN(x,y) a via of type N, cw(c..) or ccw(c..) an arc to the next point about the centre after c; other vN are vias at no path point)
+1P1: C14.1 C29.2 C30.2 C31.2 C32.2 C33.2 C34.2 R5.2 U3.1 U3.18 U3.19 U3.20 U5.1 U5.12 U5.18 U5.30 U5.34 U5.45 | length 681.9
  Top Layer w10: v1(1067.78,1497.05) 1078.47,1507.74 C29.2@1098.12,1507.74 1098.91,1508.53 U5.45@1157.47,1508.53 ; C34.2@1215.54,1300.94 v1(1215.54,1346.17) U5.1@1215.54,1391.4 1215.54,1428.99 v1(1225.18,1438.64) ; C30.2@1241.75,1803.38 1241.75,1773.32 1254.91,1760.16 U5.34@1254.91,1724.08 1254.91,1686.5 v1@1245.26,1676.85 ; v1(1333.65,1676.9) U5.30@1333.65,1724.08 1333.65,1758.54 1344.64,1769.54 C31.2@1344.64,1803.38 ; v1(1422.42,1438.64) 1432.07,1428.99 U5.12@1432.07,1391.4
  Top Layer w11: v1(1442.91,1547.9) C32.2@1569.65,1547.9
  Top Layer w18: C32.2@1569.65,1547.37 C32.2@1570.18,1547.9
  other v1: 1453.7,1385.95 892.27,1491.46 932.27,1491.46 972.27,1491.46 892.27,1521.46 932.27,1521.46 972.27,1521.46 1246.21,1676.85
+3P3: C10.1 C20.2 C21.2 C22.2 C23.2 C24.2 C25.2 C26.2 C27.2 C35.1 C39.1 J5.3 J6.3 J8.3 J9.3 R14.1 R15.2 R20.2 U4.4 U4.5 U5.7 U5.13 U5.23 U5.25 U5.33 U5.37 U5.40 U5.48 U6.9 U8.9 | length 901.3
  Top Layer w8: R14.1@1098.12,1845.74 v1(1098.12,1879)
  Top Layer w10: C21.2@1073.32,1606.95 U5.40@1157.47,1606.96 ; U5.48@1157.47,1449.48 1195.05,1449.48 v1(1204.7,1459.12) ; v1@1284.24,1676.85 1274.59,1686.5 U5.33@1274.59,1724.08 1274.59,1760.18 1292.64,1778.24 C27.2@1292.64,1803.38 ; C26.2@1293.8,1300.94 1293.8,1321.05 1333.65,1360.89 U5.7@1333.65,1391.4 1333.65,1438.59 v1(1333.7,1438.64) ; U5.25@1432.07,1724.08 1432.07,1674.6 1460.35,1646.33 U5.23@1490.14,1646.33 C24.2@1570.18,1646.33 ; v1(1442.91,1459.12) 1452.56,1449.48 U5.13@1490.14,1449.48 1527.16,1449.48 ; 1528.99,1448.4 1544.4,1432.99 1570.14,1432.99 C25.2@1570.18,1432.94
  Top Layer w16: v1(1048.7,1574.95) 1073.32,1599.57 C21.2@1073.32,1606.95
  Top Layer w18: v1(1262.25,1300.94) C26.2@1293.8,1300.94 ; v1(1572.17,1401.39) C25.2@1572.17,1432.94
  other v1: 579.42,1061.52 2472.29,1061.99 579.42,1090.64 608.53,1090.64 2472.29,1091.11 2501.41,1091.11 1150,1409.67 1285.19,1676.85 1764.54,1678 1794.54,1678 1150.7,1689.07 1166.45,1709.23 1453.24,1715.4 1764.54,1718 1794.54,1718 1472.61,1732.82 1764.54,1758 1794.54,1758 1453.36,1759.83
+5V: C5.1 C6.1 C7.1 C11.1 C18.1 C28.1 C37.1 L1.2 R1.1 R2.1 R6.2 R7.2 TP2.1 U3.5 U3.6 U3.7 U3.8 U3.10 U4.2 U6.14 U6.15 U8.14 U8.15 | length 771.6
  Top Layer w10.5: C18.1@504.43,1480.84 C18.1@504.84,1480.43 ; R7.2@523.61,1403.66 U3.10@575.9,1403.66
  Top Layer w12: 888.35,745.72 888.35,965.32 945.98,1022.95 R1.1@1211.91,1022.95 ; R2.1@1211.59,1092.54 1211.59,1023.27 R1.1@1211.91,1022.95 ; R1.1@1213.04,1021.82 R1.1@1211.91,1022.95 ; R1.1@1214.13,1022.95 R1.1@1211.91,1022.95
  Top Layer w20: U4.2@1981.03,1656.95 1981.04,1735.12
  other v1: 658.54,633 698.53,633 738.53,633 658.54,663 698.53,663 738.53,663 658.54,693 698.53,693 738.53,693 296.17,1115.88 326.17,1115.88 2189.04,1116.36 2219.04,1116.36 296.17,1155.88 326.17,1155.88 2189.04,1156.36 2219.04,1156.36 296.17,1195.88 326.17,1195.88 2185.53,1196.36 2213.53,1196.36 442.27,1401.46 482.27,1401.46 442.27,1431.46 482.27,1431.46 442.27,1471.46 1964.54,1748 1994.54,1748 1964.54,1798 1994.54,1798 1964.54,1838 1994.54,1838
DP1_CON_N: L4.1 U8.6 | length 77.1
  Top Layer w10.01: L4.1@399.32,760.23 U8.6@399.32,837.31
DP1_CON_P: L5.1 U8.5 | length 77.1
  Top Layer w10.01: L5.1@377.33,760.23 U8.5@377.33,837.31
DP1_SYS_N: U5.42 U8.11 | length 1110.4
  Top Layer w10.01: U8.11@399.23,1066.79 399.23,1114 cw(c493.23,1114) 493.23,1208 896.03,1207.99 ccw(c896.03,1330) 982.3,1243.73 ccw(c982.3,1245.16) 983.32,1244.15 989.09,1249.92 994.65,1255.48 ccw(c908.38,1341.75) 1030.38,1341.75 1030.38,1455.85 cw(c1117.32,1455.85) 1055.85,1517.32 1097.51,1558.99 cw(c1115.47,1541.03) 1115.47,1566.43 1123.93,1566.43 cw(c1125.08,1566.43) 1125.08,1567.59 U5.42@1157.47,1567.59
DP1_SYS_P: U5.41 U8.12 | length 1144.9
  Top Layer w10.01: U8.12@377.22,1066.79 377.22,1114 cw(c493.23,1114) 493.23,1230.01 896.04,1230 ccw(c896.04,1330) 966.75,1259.29 ccw(c966.75,1260.69) 967.74,1259.7 973.53,1265.49 979.09,1271.04 ccw(c908.38,1341.75) 1008.38,1341.75 1008.38,1455.85 cw(c1117.32,1455.85) 1040.29,1532.89 1081.95,1574.55 cw(c1115.47,1541.03) 1115.47,1588.42 1123.93,1588.42 ccw(c1125.08,1588.42) 1125.08,1587.27 U5.41@1157.47,1587.27
DP2_CON_N: L2.1 U6.6 | length 77.1
  Top Layer w10.01: L2.1@2292.19,760.7 U6.6@2292.19,837.79
DP2_CON_P: L3.1 U6.5 | length 77.1
  Top Layer w10.01: L3.1@2270.2,760.7 U6.5@2270.2,837.79
DP2_SYS_N: U5.15 U6.11 | length 1044.6
  Top Layer w10.01: U5.15@1490.14,1488.85 1522.05,1488.85 ; 1523.21,1490.01 1648.53,1490.01 1663.08,1490.01 cw(c1663.08,1406.55) 1722.09,1465.57 1875.36,1312.3 ccw(c1946.07,1383.01) 1946.07,1283.01 2176.1,1283.01 cw(c2176.1,1167) 2292.11,1167 U6.11@2292.11,1067.26
DP2_SYS_P: U5.14 U6.12 | length 1009.9
  Top Layer w10.01: U5.14@1490.14,1469.16 1522.05,1469.16 ; 1523.21,1468 1648.53,1468 1663.08,1468 cw(c1663.08,1406.55) 1706.54,1450 1859.8,1296.74 ccw(c1946.07,1383.01) 1946.07,1261 2176,1261 cw(c2176,1167) 2270,1167 ; U6.12@2270.1,1067.26 2270.1,1167
GND: C2.1 C3.1 C4.1 C5.2 C6.2 C7.2 C8.2 C9.1 C10.2 C11.2 C12.1 C13.1 C14.2 C15.1 C16.2 C17.2 C18.2 C19.1 C20.1 C21.1 C22.1 C23.1 C24.1 C25.1 C26.1 C27.1 C28.2 C29.1 C30.1 C31.1 C32.1 C33.1 C34.1 C35.2 C36.2 C37.2 C38.2 C39.2 D1.1 D1.2 D2.2 J2.4 J2.5 J2.6 J3.1 J4.4 J4.5 J4.6 J5.1 J6.1 J7.4 J7.5 J7.6 J8.1 J9.1 R3.2 R4.2 R9.1 R10.2 R11.2 R12.1 R13.1 R16.1 R18.1 R19.1 U1.7 U1.9 U2.3 U3.2 U3.3 U3.4 U3.12 U3.13 U3.14 U3.21 U4.3 U4.6 U5.49 U6.4 U6.13 U8.4 U8.13 | length 1455.4
  Top Layer w7: 2166.96,1243 cw(c2166.96,1159) 2250.96,1159 ; 2218.68,1230.35 cw(c2159.45,1161) 2250.65,1161 ; U6.13@2243.7,1065.77 2243.7,1100.45 2250.96,1107.71 2250.96,1161
  Top Layer w14: U8.4@350.82,850.73 U8.13@350.82,1065.3 ; 2235.63,727.23 2235.63,766.8 2238.27,769.44 2243.82,778.36 2243.7,778.36 U6.4@2243.7,851.2 U6.13@2243.7,1065.77
  Bottom Layer w19.68: v2(1363.17,1479) v2(1323.8,1479) v2(1284.43,1479) v2(1245.06,1479) v2(1245.06,1518.37) v2(1245.06,1557.74) v2(1245.06,1597.11) v2(1245.06,1636.48) v2(1284.43,1636.48) v2(1323.8,1636.48) v2(1363.17,1636.48) v2(1402.54,1636.48) v2(1402.54,1597.11) v2(1402.54,1557.74) v2(1402.54,1518.37) v2(1402.54,1479)
  other v1: 313.41,932.18 373.41,932.18 423.41,932.18 2206.29,932.65 2266.29,932.65 2316.29,932.65 313.41,992.18 2206.29,992.65 369.88,995.57 419.88,995.57 2262.76,996.05 2312.76,996.05 965.7,1722.82 1924.38,1723 1090.48,1766.14 965.76,1774.64 1922,1797.74
  other v2: 667.43,1402.68 615.27,1454.84 667.43,1454.84 719.6,1454.84 667.43,1507.01 1284.43,1518.37 1323.8,1518.37 1363.17,1518.37 1284.43,1557.74 1323.8,1557.74 1363.17,1557.74 1284.43,1597.11 1323.8,1597.11 1363.17,1597.11
  other v3: 864,537 1643.75,617.84 1839.53,617.84 1413,838 155,883.56 574,944 722,944 1763,1509 1763,1582 506,1670 1561,1805 1260,1918 1325,1918
  other v4: 1612.15,770.14 1663.33,770.14 1612.15,821.33 1663.33,821.33 1612.15,872.51 1663.33,872.51
  other v5: 799.25,1067.11 1832.13,1119.38
NetC1_1: C1.1 D1.3 L1.1 U1.8 | length 93.5
  Top Layer w12: D1.3@1561.75,682.33 v1(1602.75,682.33)
  Bottom Layer w12: v1(1602.75,682.33) C1.1@1655.25,682.33
NetC1_2: C1.2 U1.1 | length 119.3
  Top Layer w12: U1.1@1745.03,746.33 1746.73,744.62 1746.73,700.75 v1(1765.16,682.33)
  Bottom Layer w12: C1.2@1718.25,682.33 v1(1765.16,682.33)
NetC2_2: C2.2 C3.2 C4.2 J1.1 U1.2 U1.3 | length 1642.3
  Top Layer w12: C4.2@1841.24,796.33 C4.2@1841.75,796.84
  Bottom Layer w125: 1981.53,893 1981.53,1130 1660.53,1451 1660.53,1888.3 J1.1@2023.53,2251.3
  other v1: 1952.53,865 1982.53,865 2012.53,865 1952.53,905 1982.53,905 2012.53,905 1952.53,945 1982.53,945 2012.53,945
NetC9_2: C9.2 U1.6 | length 63.9
  Top Layer w12: C9.2@1466.74,846.7 C9.2@1467.12,846.33
  Top Layer w22: C9.2@1467.12,846.33 U1.6@1530.46,846.33
NetC12_2: C12.2 R6.1 U4.1
NetC13_2: C13.2 R7.1 U3.11
NetC15_2: C15.2 U5.11 | length 167.6
  Top Layer w6: U5.11@1412.39,1391.4 1412.39,1360.57 1422.2,1350.75 1486.53,1350.75 1507.66,1329.61 C15.2@1507.66,1300.94
NetC16_1: C16.1 R8.1 U5.39 Y1.1 | length 275.6
  Top Layer w6: C16.1@1011.17,1663.14 C16.1@1012.55,1664.52 C16.1@1014.36,1666.34 ; R8.1@1064.49,1664.52 1065.97,1663.03 1084.88,1663.03 1121.27,1626.64 U5.39@1157.47,1626.64
  Top Layer w18: v1(974.76,1663.14) C16.1@1011.17,1663.14 ; C16.1@1014.36,1663.14 R8.1@1064.49,1663.14
  Bottom Layer w6: Y1.1@901.36,1669.14 Y1.1@907.36,1663.14
  Bottom Layer w18: Y1.1@907.36,1663.14 v1(974.76,1663.14)
NetC17_1: C17.1 R8.2 U5.38 Y1.2 | length 385.4
  Top Layer w6: C17.1@1010.25,1818.43 C17.1@1012.55,1816.13 ; R8.2@1064.49,1713.58 1086.62,1713.58 1106.5,1693.7 1106.5,1664.97 1125.15,1646.33 U5.38@1157.47,1646.33
  Top Layer w18: v1@974.76,1818.43 C17.1@1010.25,1818.43 ; C17.1@1012.55,1816.13 1031.67,1816.13 1064.49,1783.31 R8.2@1064.49,1713.58
  Bottom Layer w6: Y1.2@901.36,1818.75 Y1.2@902.28,1817.83
  Bottom Layer w18: Y1.2@902.28,1817.83 v1(974.76,1817.83)
NetC19_2: C19.2 U3.15
NetC36_1: C36.1 J4.1 U6.2 U6.3
  other v1: 2165.62,765.41 2206.9,771.51 2165.62,795.41 2206.9,801.51
NetC38_1: C38.1 J7.1 U8.2 U8.3
  other v1: 272.75,764.93 314.02,771.04 272.75,794.93 314.02,801.04
NetD2_1: D2.1 R2.2 | length 87.5
  Top Layer w12: R2.2@1257.48,1091.85 1293.62,1091.85 ; 1293.62,1091.62 1303.62,1101.63 D2.1@1340.79,1101.63
NetJ4_2: J4.2 T1.4 | length 121.5
  Top Layer w10.01: T1.4@2292.53,617 2292.53,540.38 ccw(c2320.91,540.38) J4.2@2320.91,512
  Top Layer w11: T1.4@2292.19,617 T1.4@2292.53,617
NetJ4_3: J4.3 T1.2 | length 121.2
  Top Layer w10.01: J4.3@2242.16,512 ccw(c2242.16,540.37) 2270.54,540.37 T1.2@2270.54,617
NetJ5_2: J5.2 U6.7 | length 831.5
  Top Layer w12: U6.7@2318.7,851.2 2318.7,805.69 2328.15,796.24 v1(2358.42,796.24)
  Bottom Layer w12: v1(2358.42,796.24) 2403.99,796.24 2411.49,803.74 2435.54,827.8 2435.54,1012.08 2326.12,1121.51 2326.12,1326.58 J5.2@2402.54,1403
NetJ6_2: J6.2 U6.8 | length 1059
  Top Layer w12: U6.8@2343.7,851.2 v1(2381.92,851.2)
  Bottom Layer w12: v1(2381.92,851.2) 2381.92,999.39 2288.09,1093.22 2288.09,1671.28 J6.2@2402.54,1785.73
NetJ7_2: J7.2 T2.4 | length 121.5
  Top Layer w10.01: T2.4@400.03,615.87 400.03,539.24 ccw(c428.41,539.24) J7.2@428.41,510.87
  Top Layer w11: T2.4@399.7,615.87 T2.4@400.03,615.87
NetJ7_3: J7.3 T2.2 | length 121.2
  Top Layer w10.01: J7.3@349.67,510.87 ccw(c349.67,539.24) 378.04,539.24 T2.2@378.04,615.87
NetJ8_2: J8.2 U8.7 | length 880.3
  Top Layer w12: v1(424.7,801.41) 425.82,802.54 U8.7@425.82,850.73
  Bottom Layer w12: J8.2@243.59,1455.52 316.82,1382.29 316.82,1287.24 226.8,1197.22 226.8,953.52 378.91,801.41 v1(424.7,801.41)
